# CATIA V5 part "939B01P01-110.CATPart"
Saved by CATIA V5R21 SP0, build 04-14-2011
Part number: 939B01P01-110
Bounding box of the stored display mesh (mm): x -17.1 to 17.1, y -76.2 to 76.2, z -4.4 to 105.6
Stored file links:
  C:\Users\ALI OZGUN\Desktop\alhan\939B01P01-110.CATPart
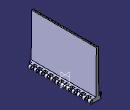
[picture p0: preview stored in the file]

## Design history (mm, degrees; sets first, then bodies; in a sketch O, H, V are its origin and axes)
Body1 (main body)
  Sketch1 on zx-plane, origin (0, 0, 0), H (-1, 0, 0), V (0, 0, 1)
    construction line L1 (-12.7, 0) -> (12.7, 0)
    point P1 (-12.7, 0)
    line L2 (-12.7, 4.4) -> (12.7, 4.4)
    line L3 (12.7, -4.4) -> (-12.7, -4.4)
    arc A1 centre (12.7, 0) radius 4.4 from (12.7, 4.4) to (12.7, -4.4) cw
    arc A2 centre (-12.7, 0) radius 4.4 from (-12.7, -4.4) to (-12.7, 4.4) cw
    distance L1 L2 = 4.4
    length L1 = 25.4
    distance P1 V = 12.7
    coincidence: P1 H
    horizontal: L1 H
    tangency: A1 L2, A2 L2, A1 L3, A2 L3
  Pad1: profile Sketch1, direction (0, 1, 0), length 76.2, mirrored extent
  Sketch2 on face of Pad1 from Sketch1.L2, origin (0, 0, 4.4), H (1, 0, 0), V (0, 1, 0)
    line L1 (-22.3127, -63.5) -> (-9.75, -63.5)
    line L2 (-9.75, -63.5) -> (-9.75, -70.6)
    line L3 (-9.75, -70.6) -> (-22.3127, -70.6)
    line L4 (-22.3127, -70.6) -> (-22.3127, -63.5)
    line L5 (24.6678, -76.95) -> (9.75, -76.95)
    line L6 (9.75, -76.95) -> (9.75, -69.85)
    line L7 (9.75, -69.85) -> (24.6678, -69.85)
    line L8 (24.6678, -69.85) -> (24.6678, -76.95)
    reference projected line E1 (-12.7, -76.2) -> (12.7, -76.2) from edge [start face of Pad1 | face of Pad1 from Sketch1.L2]
    reference projected line E2 (-12.7, -76.2) -> (12.7, -76.2) from edge [start face of Pad1 | face of Pad1 from Sketch1.L2]
    distance L3 E1 = 5.6
    length L4 = 7.1
    distance L7 L5 = 7.1
    distance L5 E2 = 0.75
    distance L2 L6 = 19.5
    distance L2 V = 9.75
    horizontal: L1 H, L3 H, L5 H, L7 H
    vertical: L2 V, L4 V, L6 V, L8 V
  Pocket1: profile Sketch2, direction (0, 0, -1), length 76.2
  RectPattern1: of Pocket1, direction 1 instances 12, spacing 12.7, along axis of face of Pad1 from Sketch1.A2
  Sketch3 on face of Pad1 from Sketch1.L3, origin (0, 0, -4.4), H (1, 0, 0), V (0, -1, 0)
    line L1 (-6.5, -54.6) -> (6.5, -54.6)
    line L2 (6.5, -54.6) -> (6.5, -73.7)
    line L3 (6.5, -73.7) -> (-6.5, -73.7)
    line L4 (-6.5, -73.7) -> (-6.5, -54.6)
    construction line L5 (-4.5, -51.1) -> (4.5, -51.1)
    point P5 (-4.5, -51.1)
    line L6 (-4.5, -49.6) -> (4.5, -49.6)
    line L7 (4.5, -52.6) -> (-4.5, -52.6)
    arc A1 centre (4.5, -51.1) radius 1.5 from (4.5, -49.6) to (4.5, -52.6) cw
    arc A2 centre (-4.5, -51.1) radius 1.5 from (-4.5, -52.6) to (-4.5, -49.6) cw
    reference projected line E1 (12.7, -76.2) -> (-12.7, -76.2) from edge [face of Pad1 from Sketch1.L3 | end face of Pad1]
    distance L5 L6 = 1.5
    distance L1 L3 = 19.1
    distance L4 L2 = 13
    distance L4 V = 6.5
    distance E1 L3 = 2.5
    distance P5 V = 4.5
    length L5 = 9
    distance L7 L1 = 2
    horizontal: L1 H, L3 H, L5 H
    vertical: L2 V, L4 V
    tangency: A1 L6, A2 L6, A1 L7, A2 L7
  Pocket2: profile Sketch3, direction (0, 0, 1), length 6
  RectPattern2: of Pocket2, direction 1 instances 6, spacing 25.8, along axis of face of Pad1 from Sketch1.A2 reversed
  Sketch4 on zx-plane, origin (0, 0, 0), H (-1, 0, 0), V (0, 0, 1)
    circle A1 centre (12.7, 0) radius 2.3
    point P1 (12.7, 0)
    circle A2 centre (-12.7, 0) radius 2.3
    point P2 (-12.7, 0)
    reference projected arc E1 centre (12.7, 0) radius 4.4 from (12.7, -4.4) to (12.7, 4.4) ccw from edge [face of RectPattern1 | face of Pad1 from Sketch1.A1]
    reference projected arc E2 centre (-12.7, 0) radius 4.4 from (-12.7, 4.4) to (-12.7, -4.4) ccw from edge [face of Pad1 from Sketch1.A2 | end face of Pad1]
    radius A1 = 2.3
    radius A2 = 2.3
    coincidence: P1 H, P2 H
    concentricity: P1 E1, A2 E2
  Pocket3: profile Sketch4, direction (0, -1, 0), length 97.8, mirrored extent
  Body2
    Solid1: linked copy from another document
    Symmetry1: Reference yz-plane, ToTransfor Solid1
    Translate1: Direction edge [face of Pocket1 from Sketch2.L2 | face of Pad1 from Sketch1.L3], Length 6.35, ToTransfor Symmetry1
    Body3
      Sketch5 on face of RectPattern1, origin (9.75, 0, 0), H (0, 1, 0), V (0, 0, 1)
      Pad2: profile Sketch5, direction (1, 0, 0), length 12
      Sketch6 on face of Pad2, origin (0, 69.85, 0), H (-1, 0, 0), V (0, 0, 1)
        point P2 (-21.75, 4.4)
        arc A1 centre (-16.4898, 1.5645) radius 9 from (-9.75, -4.4) to (-7.9481, 4.4) ccw
        point P8 (-21.75, 4.4)
        construction line L1 (-9.75, 4.4) -> (-21.75, 4.4)
        line L2 (-7.9481, 4.4) -> (-21.75, 4.4)
        line L3 (-9.75, -4.4) -> (-21.75, -4.4)
        line L4 (-21.75, -4.4) -> (-21.75, 4.4)
        radius A1 = 9
        coincidence: P2 P8
      Pad3: profile Sketch6, direction (0, 1, 0), up to face of Pad2
      RectPattern3: of the body so far, direction 1 instances 12, spacing 12.7, along edge [face of Pad3 | face of Pad3] reversed
    Add1: tool Body3
  Remove1: tool Body2
  Sketch7 on zx-plane, origin (0, 0, 0), H (-1, 0, 0), V (0, 0, 1)
    projected line E1 (7.9481, 4.4) -> (-12.7, 4.4) from edge [face of Pad1 from Sketch1.L2 | end face of Pad1]
    projected line E2 (3.2, 4.4) -> (-3.2, 4.4) from edge [face of Pad1 from Sketch1.L2 | end face of Pad1]
    point P3 (-3.2, 4.4)
    line L1 (-3.2, 4.4) -> (-2, 105.6)
    point P4 (-2, 105.6)
    line L2 (-2, 105.6) -> (2, 105.6)
    line L3 (2, 105.6) -> (3.2, 4.4)
    reference projected line E3 (-12.7, -4.4) -> (12.7, -4.4) from edge [face of Pad1 from Sketch1.L3 | end face of Pad1]
    distance L2 E3 = 110
    distance P3 V = 3.2
    distance P4 V = 2
    coincidence: P3 E1, P3 L1
    horizontal: L2 H
    symmetry: L1 L3 V
  Pad4: profile Sketch7, direction (0, 1, 0), length 76.2, mirrored extent
  Fillet1: radius 1, on edge [face of Pad4 from Sketch7.L2 | face of Pad4 from Sketch7.L3]; edge [face of Pad4 from Sketch7.L1 | face of Pad4 from Sketch7.L2]
Body4
  Solid2: linked copy from another document
  Translate2: Direction yz-plane, Length 25.4, ToTransfor Solid2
